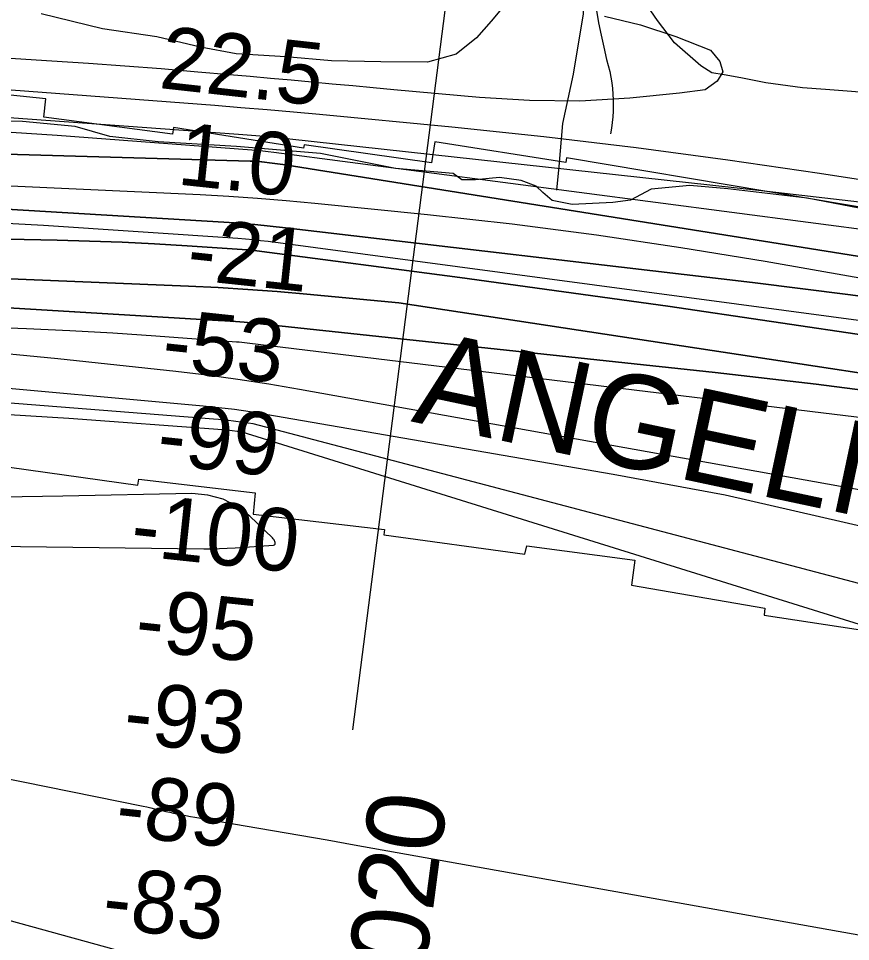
# Model space of a CAD drawing. Extents: x 3477039 to 3515015, y 546746 to 572297.
# Drawn here: x 3495983 to 3496874, y 565048 to 566036 of the extents above; entities that cross this region are included whole.
import ezdxf

# ---------------------------------------------------------------- set-up
doc = ezdxf.new("R2010")
doc.units = 0
for name, color, linetype in [('V-RIVR-EDGE', 7, 'Continuous'), ('V-RIVR-RANG', 7, 'Continuous'), ('V-RIVR-RANG-IDEN', 7, 'Continuous'), ('V-ROAD-CNTR', 7, 'Continuous'), ('V-RRAP-RVMT', 7, 'Continuous'), ('V-RRAP-RVMT-IDEN', 7, 'Continuous'), ('V-SITE-VEGE', 7, 'Continuous'), ('V-TOPO-DPTH', 7, 'Continuous'), ('V-TOPO-MAJR', 7, 'Continuous'), ('V-TOPO-MINR', 7, 'Continuous'), ('V-TOPO-WATR', 7, 'Continuous')]:
    doc.layers.add(name, color=color, linetype=linetype)

msp = doc.modelspace()

# ---------------------------------------------------------------- linework, layer by layer
at = {"layer": 'V-RIVR-EDGE'}
msp.add_lwpolyline([(3496957.3, 565818.57), (3496827.47, 565843.4), (3496742.32, 565853.41), (3496701.89, 565857.19), (3496660.21, 565853), (3496638.13, 565841.42), (3496619.13, 565839.01), (3496575.62, 565836.67), (3496554.18, 565841.01), (3496544.4, 565849.61), (3496537.06, 565856.37), (3496521.15, 565862.54), (3496497.87, 565865.66), (3496472.13, 565863.27), (3496457.43, 565863.31), (3496448.25, 565870.07), (3496386.38, 565875.13), (3496306.15, 565891.26), (3496216.1, 565898.83), (3496132.17, 565903.94), (3496080.71, 565909.58), (3496043.36, 565920.09), (3495987.01, 565925.74), (3495880.4, 565928.46)], dxfattribs=at)
at = {"layer": 'V-RIVR-RANG'}
msp.add_line((3496478.2, 566345.66), (3496340.49, 565274.48), dxfattribs=at)
at = {"layer": 'V-ROAD-CNTR'}
for points in [[(3496246.34, 566507.57), (3496245.2, 566482.09), (3496242.29, 566469.09), (3496260.5, 566457.13), (3496304.77, 566431.33), (3496358.02, 566406.36), (3496399.15, 566379.95), (3496450.2, 566355.13), (3496501.38, 566320.35), (3496535.86, 566296.37), (3496563.48, 566267.26), (3496579.75, 566242.09), (3496587.69, 566212.48), (3496588.84, 566175.79), (3496589.71, 566095.32), (3496587.65, 566040.76), (3496576.72, 565976.38), (3496565.34, 565923.65), (3496561.27, 565877.28), (3496558.82, 565852.14)], [(3496601.6, 566044.37), (3496604.05, 566031.24), (3496606.7, 566018.15), (3496609.56, 566005.1), (3496612.62, 565992.1), (3496615.88, 565979.14)], [(3496615.88, 565979.14), (3496617.09, 565973.15), (3496618.08, 565967.11), (3496618.84, 565961.04), (3496619.37, 565954.94), (3496619.67, 565948.83), (3496619.74, 565942.71), (3496619.58, 565936.6), (3496619.19, 565930.49), (3496618.58, 565924.4), (3496617.73, 565918.35), (3496616.65, 565912.33)]]:
    msp.add_lwpolyline(points, dxfattribs=at)
at = {"layer": 'V-RRAP-RVMT'}
for points in [[(3496428.75, 565903.82), (3496425.03, 565881.3), (3496288.73, 565900.79), (3496288.13, 565897.23), (3496148.81, 565919.33), (3496147.48, 565912.06), (3496010.02, 565930.31), (3496012.05, 565950.05), (3495887.88, 565962.86)], [(3498017.81, 565575.45), (3497871.45, 565614.89), (3497875.49, 565636.07), (3497723.36, 565670.25), (3497726.6, 565689.16), (3497585.89, 565716.82), (3497587.48, 565727.34), (3497446.64, 565753.6), (3497447.28, 565757.54), (3497148.03, 565804.73), (3497146.14, 565793.55), (3497004.18, 565819.67), (3497003.06, 565813.83), (3496569.66, 565886.55), (3496568.88, 565881.74), (3496428.75, 565903.82)], [(3495952.43, 565558.58), (3496110.6, 565536.17), (3496111.72, 565542.55), (3496236.14, 565527.94), (3496234.08, 565505.3), (3496374.74, 565488.82), (3496374.09, 565483.16), (3496525.18, 565462.33), (3496526.99, 565471.5), (3496642.67, 565455.88), (3496639.22, 565429.11), (3496782.19, 565404.78), (3496781.48, 565397.29), (3496929.02, 565374.81)]]:
    msp.add_lwpolyline(points, dxfattribs=at)
at = {"layer": 'V-SITE-VEGE'}
for points in [[(3497120.6, 566047.4), (3497218.33, 566003.77), (3497290.1, 565964.74), (3497333.04, 565944.44), (3497349.29, 565930.24), (3497355.18, 565922.04), (3497354.38, 565913.14), (3497347.63, 565900.56), (3497322.32, 565889.57), (3497261.49, 565895.87), (3497147.27, 565912.88), (3497006.37, 565938.21), (3496907, 565955.13), (3496846.9, 565959.94), (3496822.41, 565961.57), (3496783.1, 565967), (3496756.41, 565972.36), (3496738.61, 565975.43), (3496725.26, 565977.74), (3496713.43, 565985.23), (3496685.37, 566009.9), (3496666.95, 566033.76), (3496652.23, 566055.38)], [(3496503.68, 566050.45), (3496488.87, 566032.88), (3496473.08, 566015.31), (3496451.4, 565997.78), (3496420.94, 565989.12), (3496370.92, 565989.4), (3496317.95, 565990.68), (3496268.93, 565994.88), (3496215.98, 565998.12), (3496177.77, 566005.2), (3496130.74, 566016.26), (3496072.67, 566024.93), (3496006.92, 566040.72)]]:
    msp.add_lwpolyline(points, dxfattribs=at)
at = {"layer": 'V-TOPO-DPTH'}
for points in [[(3498160.46, 565543.63), (3497431.39, 565755.67), (3497421.88, 565758), (3497412.28, 565759.98), (3497402.63, 565761.72), (3497206.95, 565793.33), (3497099.32, 565809.88), (3496991.53, 565825.32), (3496883.52, 565839.1), (3496775.35, 565851.78), (3496273.4, 565906.72), (3496259.69, 565908.14), (3496245.98, 565909.46), (3496232.25, 565910.64), (3496218.51, 565911.71), (3495486.1, 565964.87)], [(3498512.82, 565373.8), (3497462.6, 565684.44), (3497434.89, 565690.67), (3497407.09, 565696.49), (3497379.18, 565701.69), (3497351.18, 565706.48), (3496277.27, 565877.71), (3496271.58, 565878.6), (3496265.88, 565879.45), (3496260.18, 565880.26), (3496254.47, 565881.03), (3496243.27, 565882.51), (3496243.04, 565882.54), (3496238.94, 565882.84), (3496236.89, 565882.98), (3496232.78, 565883.19), (3496230.72, 565883.27), (3494996.72, 565918.61)], [(3494996.72, 565918.61), (3496230.72, 565883.27), (3496232.78, 565883.19), (3496236.89, 565882.98), (3496238.94, 565882.84), (3496243.04, 565882.54), (3496243.27, 565882.51), (3496254.47, 565881.03), (3496260.18, 565880.26), (3496265.88, 565879.45), (3496271.58, 565878.6), (3496277.27, 565877.71), (3497351.18, 565706.48), (3497379.18, 565701.69), (3497407.09, 565696.49), (3497434.89, 565690.67), (3497462.6, 565684.44), (3498512.82, 565373.8)], [(3498451.12, 565366.82), (3497409.8, 565651.62), (3497403.42, 565653.27), (3497397.01, 565654.8), (3497390.57, 565656.16), (3497384.09, 565657.39), (3497188.25, 565691.92), (3497083.7, 565709.41), (3496978.98, 565725.7), (3496873.98, 565740.15), (3496768.81, 565753.39), (3496268.64, 565811.95), (3496252.2, 565813.73), (3496235.74, 565815.32), (3496219.25, 565816.64), (3496202.75, 565817.76), (3495712.9, 565846.95)], [(3495712.9, 565846.95), (3496202.75, 565817.76), (3496219.25, 565816.64), (3496235.74, 565815.32), (3496252.2, 565813.73), (3496268.64, 565811.95), (3496768.81, 565753.39), (3496873.98, 565740.15), (3496978.98, 565725.7), (3497083.7, 565709.41), (3497188.25, 565691.92), (3497384.09, 565657.39), (3497390.57, 565656.16), (3497397.01, 565654.8), (3497403.42, 565653.27), (3497409.8, 565651.62), (3498451.12, 565366.82)], [(3494999.93, 565819.44), (3496024.06, 565798.6), (3496058.88, 565797.66), (3496093.68, 565796.39), (3496128.47, 565794.64), (3496163.23, 565792.58), (3496227.66, 565788.31), (3496230.21, 565788.11), (3496232.74, 565787.89), (3496235.28, 565787.61), (3496237.81, 565787.3), (3496455.46, 565758.45), (3496566.77, 565743.35), (3496678.01, 565727.81), (3496789.16, 565711.6), (3496900.24, 565694.94), (3497312.27, 565631.89), (3497350.4, 565625.68), (3497388.45, 565618.99), (3497426.35, 565611.57), (3497464.17, 565603.68), (3497474.32, 565601.45), (3498461.05, 565311.54)], [(3494999.93, 565819.44), (3496024.06, 565798.6), (3496058.88, 565797.66), (3496093.68, 565796.39), (3496128.47, 565794.64), (3496163.23, 565792.58), (3496227.66, 565788.31), (3496230.21, 565788.11), (3496232.74, 565787.89), (3496235.28, 565787.61), (3496237.81, 565787.3), (3496455.46, 565758.45), (3496566.77, 565743.35), (3496678.01, 565727.81), (3496789.16, 565711.6), (3496900.24, 565694.94), (3497312.27, 565631.89), (3497350.4, 565625.68), (3497388.45, 565618.99), (3497426.35, 565611.57), (3497464.17, 565603.68), (3497474.32, 565601.45), (3498461.05, 565311.54)], [(3498478.51, 565276.24), (3497648.13, 565517.56), (3497414.72, 565572.26), (3497396.89, 565576.24), (3497379.01, 565579.99), (3497361.06, 565583.37), (3497343.06, 565586.5), (3496389.9, 565731.45), (3496291.58, 565740.73), (3496259.9, 565743.47), (3496228.21, 565745.87), (3496196.48, 565747.76), (3496164.72, 565749.31), (3495321.12, 565783.85)], [(3495321.12, 565783.85), (3496164.72, 565749.31), (3496196.48, 565747.76), (3496228.21, 565745.87), (3496259.9, 565743.47), (3496291.58, 565740.73), (3496389.9, 565731.45), (3497343.06, 565586.5), (3497361.06, 565583.37), (3497379.01, 565579.99), (3497396.89, 565576.24), (3497414.72, 565572.26), (3497648.13, 565517.56), (3498478.51, 565276.24)], [(3498486.89, 565258.7), (3497389.54, 565556.43), (3497381.88, 565558.32), (3497374.2, 565560.08), (3497366.47, 565561.64), (3497358.71, 565563.07), (3497159.74, 565597.17), (3497052.34, 565614.53), (3496944.75, 565630.53), (3496836.87, 565644.49), (3496728.8, 565657.09), (3496251.97, 565708.12), (3496238.17, 565709.5), (3496224.36, 565710.75), (3496210.53, 565711.8), (3496196.7, 565712.73), (3495888.85, 565731.14)], [(3495888.85, 565731.14), (3496196.7, 565712.73), (3496210.53, 565711.8), (3496224.36, 565710.75), (3496238.17, 565709.5), (3496251.97, 565708.12), (3496728.8, 565657.09), (3496836.87, 565644.49), (3496944.75, 565630.53), (3497052.34, 565614.53), (3497159.74, 565597.17), (3497358.71, 565563.07), (3497366.47, 565561.64), (3497374.2, 565560.08), (3497381.88, 565558.32), (3497389.54, 565556.43), (3498486.89, 565258.7)]]:
    msp.add_lwpolyline(points, dxfattribs=at)
at = {"layer": 'V-TOPO-MAJR'}
for points in [[(3498420.51, 565227.87), (3497577.65, 565489.3), (3497526.11, 565504.1), (3497474.46, 565518.55), (3497372.86, 565546.41), (3497370.07, 565547.07), (3497369.13, 565547.24), (3497345.59, 565551.26), (3497332.87, 565553.33), (3497320.12, 565555.29), (3497307.35, 565557.06), (3497294.56, 565558.7), (3496227.65, 565688.46), (3496224.83, 565688.78), (3496222, 565689.07), (3496219.17, 565689.33), (3496216.33, 565689.56), (3496129.8, 565695.86), (3496083.68, 565698.93), (3496037.54, 565701.62), (3495991.38, 565703.73), (3495945.19, 565705.47)], [(3496256.49, 565477.67), (3496255.63, 565478.83), (3496254.65, 565479.92), (3496230.65, 565503.04), (3496216.74, 565513.51), (3496201.87, 565521.48), (3496185.53, 565525.72), (3496168.22, 565527.46), (3496030.11, 565524.54), (3495942.91, 565522.93)], [(3495451.21, 565477.43), (3496181.2, 565468.21), (3496189.58, 565468.21), (3496197.95, 565468.35), (3496206.31, 565468.69), (3496214.68, 565469.17), (3496255.79, 565472.06), (3496256.81, 565472.47), (3496257.52, 565473.07), (3496257.79, 565473.97), (3496257.77, 565475.06), (3496256.49, 565477.67)]]:
    msp.add_lwpolyline(points, dxfattribs=at)
at = {"layer": 'V-TOPO-MINR'}
for points in [[(3496610.2, 566038.46), (3496648.87, 566028.93), (3496686.7, 566016.48), (3496723.96, 566002.1), (3496733.82, 565989.93), (3496737.21, 565978.64), (3496730.92, 565968.68), (3496718.15, 565959.6), (3496690.77, 565955.89), (3496637.29, 565950.49), (3496583.76, 565947.5), (3496530.14, 565948.16), (3496476.48, 565951.23), (3496384.7, 565959.62), (3496362.71, 565961.63), (3496340.72, 565963.65), (3496318.72, 565965.68), (3496296.73, 565967.71), (3496274.74, 565969.72), (3496252.74, 565971.71), (3496230.74, 565973.67), (3496208.74, 565975.6), (3496174.7, 565978.57), (3496135.67, 565981.84), (3496096.62, 565984.92), (3496057.56, 565987.74), (3496018.47, 565990.38), (3495030.91, 566053.6)], [(3498148.35, 565588.94), (3497719.16, 565706.24), (3497466.89, 565769.46), (3497446.9, 565774.17), (3497426.84, 565778.51), (3497406.67, 565782.3), (3497386.43, 565785.72), (3496840.72, 565870.07), (3496742.49, 565884.39), (3496644.11, 565897.57), (3496545.52, 565909.04), (3496446.79, 565919.38), (3496305.22, 565932.96), (3496277.16, 565935.57), (3496249.09, 565938.06), (3496221, 565940.39), (3496192.91, 565942.6), (3495637.84, 565984.62)], [(3498160.46, 565543.63), (3497431.39, 565755.67), (3497421.88, 565758), (3497412.28, 565759.98), (3497402.63, 565761.72), (3497206.95, 565793.33), (3497099.32, 565809.88), (3496991.53, 565825.32), (3496883.52, 565839.1), (3496775.35, 565851.78), (3496273.4, 565906.72), (3496259.69, 565908.14), (3496245.98, 565909.46), (3496232.25, 565910.64), (3496218.51, 565911.71), (3495486.1, 565964.87)], [(3498546.98, 565389.41), (3497441.94, 565732.9), (3497435.85, 565734.7), (3497429.74, 565736.46), (3497417.96, 565739.82), (3497417.29, 565739.98), (3497417.06, 565740.02), (3497411.93, 565740.88), (3497409.13, 565741.33), (3497406.33, 565741.76), (3497403.53, 565742.16), (3497400.72, 565742.54), (3496256.01, 565892.52), (3496250.15, 565893.24), (3496244.28, 565893.89), (3496238.4, 565894.45), (3496232.52, 565894.94), (3496024.21, 565910.68), (3495914.12, 565917.91)], [(3498520.98, 565356.7), (3497424.76, 565660.89), (3497412.34, 565663.87), (3497399.88, 565666.67), (3497387.36, 565669.2), (3497374.8, 565671.55), (3496782.33, 565775.73), (3496692.22, 565790.55), (3496601.94, 565804.06), (3496511.38, 565815.58), (3496420.63, 565825.78), (3496300.21, 565837.97), (3496269.52, 565840.83), (3496238.81, 565843.34), (3496208.06, 565845.35), (3496177.29, 565847.02), (3495239.54, 565890.07)], [(3498451.12, 565366.82), (3497409.8, 565651.62), (3497403.42, 565653.27), (3497397.01, 565654.8), (3497390.57, 565656.16), (3497384.09, 565657.39), (3497188.25, 565691.92), (3497083.7, 565709.41), (3496978.98, 565725.7), (3496873.98, 565740.15), (3496768.81, 565753.39), (3496268.64, 565811.95), (3496252.2, 565813.73), (3496235.74, 565815.32), (3496219.25, 565816.64), (3496202.75, 565817.76), (3495712.9, 565846.95)], [(3498461.05, 565311.54), (3497474.32, 565601.45), (3497464.17, 565603.68), (3497426.35, 565611.57), (3497388.45, 565618.99), (3497350.4, 565625.68), (3497312.27, 565631.89), (3496900.24, 565694.94), (3496789.16, 565711.6), (3496678.01, 565727.81), (3496566.77, 565743.35), (3496455.46, 565758.45), (3496237.81, 565787.3), (3496235.28, 565787.61), (3496232.74, 565787.89), (3496230.21, 565788.11), (3496227.66, 565788.31), (3496163.23, 565792.58), (3496128.47, 565794.64), (3496093.68, 565796.39), (3496058.88, 565797.66), (3496024.06, 565798.6), (3494999.93, 565819.44)], [(3498460.87, 565336.42), (3497503.13, 565613.11), (3497475.92, 565620.69), (3497448.68, 565628.19), (3497394.97, 565642.86), (3497394.57, 565642.96), (3497393.38, 565643.22), (3497381.04, 565645.4), (3497374.46, 565646.52), (3497367.88, 565647.58), (3497361.28, 565648.56), (3497354.68, 565649.49), (3496250.21, 565797.02), (3496242.08, 565798.02), (3496233.95, 565798.91), (3496225.79, 565799.65), (3496217.63, 565800.27), (3496009.4, 565814.12), (3495897.08, 565820.51)], [(3498478.51, 565276.24), (3497648.13, 565517.56), (3497414.72, 565572.26), (3497396.89, 565576.24), (3497379.01, 565579.99), (3497361.06, 565583.37), (3497343.06, 565586.5), (3496389.9, 565731.45), (3496291.58, 565740.73), (3496259.9, 565743.47), (3496228.21, 565745.87), (3496196.48, 565747.76), (3496164.72, 565749.31), (3495321.12, 565783.85)], [(3498486.89, 565258.7), (3497389.54, 565556.43), (3497381.88, 565558.32), (3497374.2, 565560.08), (3497366.47, 565561.64), (3497358.71, 565563.07), (3497159.74, 565597.17), (3497052.34, 565614.53), (3496944.75, 565630.53), (3496836.87, 565644.49), (3496728.8, 565657.09), (3496251.97, 565708.12), (3496238.17, 565709.5), (3496224.36, 565710.75), (3496210.53, 565711.8), (3496196.7, 565712.73), (3495888.85, 565731.14)], [(3498399.12, 565102.96), (3497397.61, 565366.85), (3497364.46, 565374.47), (3497331.38, 565382.34), (3497298.38, 565390.59), (3497265.45, 565399.09), (3497095.56, 565443.98), (3496739.46, 565525.44), (3496619.7, 565547.76), (3496247.71, 565612.04), (3496230.95, 565614.73), (3496214.16, 565617.15), (3496197.32, 565619.16), (3496180.43, 565620.9), (3495377.96, 565693.82)], [(3498448.45, 565154.2), (3497414.25, 565430.11), (3497397.48, 565434.57), (3497380.71, 565439.02), (3497347.19, 565447.9), (3497344.43, 565448.45), (3497341.69, 565448.98), (3497338.95, 565449.48), (3496283.8, 565638.86), (3496250.76, 565644.43), (3496217.66, 565649.54), (3496184.45, 565653.95), (3496151.18, 565657.88), (3496024.87, 565671.49), (3495928.32, 565680.91)], [(3498424.45, 565075.39), (3497290.41, 565311.85), (3497267.93, 565318.14), (3497094.98, 565367.9), (3497065.47, 565377.03), (3497036.25, 565386.95), (3497007.45, 565398.04), (3496234.07, 565601.81), (3496223.47, 565603.47), (3496212.84, 565604.93), (3496202.18, 565606.11), (3496191.49, 565607.09), (3495588.21, 565654.3)], [(3498302.74, 565009.38), (3497392.96, 565236.18), (3497347.39, 565247.89), (3497301.91, 565259.91), (3497256.55, 565272.38), (3497211.27, 565285.16), (3496222.27, 565592.9), (3496216.99, 565593.72), (3496211.7, 565594.44), (3496206.4, 565595.01), (3496201.08, 565595.48), (3496036.6, 565607.62), (3495949, 565613.02)], [(3495858.79, 565244.78), (3496116.27, 565192.68), (3496120.34, 565191.83), (3496124.4, 565190.94), (3496128.44, 565189.99), (3496132.48, 565189.01), (3496136.52, 565188.03), (3496140.56, 565187.08), (3496144.62, 565186.19), (3496148.69, 565185.33), (3496162.1, 565182.59), (3496166.83, 565181.67), (3496171.57, 565180.82), (3496225.37, 565171.7), (3496254.64, 565166.7), (3496283.9, 565161.65), (3496313.14, 565156.52), (3496342.38, 565151.35), (3497206.92, 564997.14)], [(3495949.71, 565076.79), (3496086.08, 565039.15)]]:
    msp.add_lwpolyline(points, dxfattribs=at)
at = {"layer": 'V-TOPO-WATR'}
msp.add_lwpolyline([(3498512.82, 565373.8), (3497462.6, 565684.44), (3497434.89, 565690.67), (3497407.09, 565696.49), (3497379.18, 565701.69), (3497351.18, 565706.48), (3496277.27, 565877.71), (3496271.58, 565878.6), (3496265.88, 565879.45), (3496260.18, 565880.26), (3496254.47, 565881.03), (3496243.27, 565882.51), (3496243.04, 565882.54), (3496238.94, 565882.84), (3496236.89, 565882.98), (3496232.78, 565883.19), (3496230.72, 565883.27), (3494996.72, 565918.61)], dxfattribs=at)

# ---------------------------------------------------------------- texts
at = {"layer": 'V-RIVR-RANG'}
for s, rotation, p in [('22.5', 353.64833, (3496132.15, 565961.57)), ('1.0', 353.93519, (3496151.6, 565858.34)), ('-21', 353.93519, (3496161.52, 565756.72)), ('-53', 353.93519, (3496134.7, 565659.01)), ('-99', 353.93519, (3496129.4, 565559.01)), ('-100', 353.93519, (3496101.28, 565461.44)), ('-95', 353.93519, (3496105.94, 565360.38)), ('-93', 353.93519, (3496093.56, 565261.13)), ('-89', 353.93519, (3496085.11, 565161.47)), ('-83', 353.93519, (3496070.89, 565062.41))]:
    msp.add_text(s, height=67, rotation=rotation, dxfattribs=at).set_placement(p)
at = {"layer": 'V-RIVR-RANG-IDEN'}
msp.add_text('D-020', height=83, rotation=82.53233, dxfattribs=at).set_placement((3496403.08, 564901.48))
at = {"layer": 'V-RRAP-RVMT-IDEN'}
msp.add_text('ANGELINA', height=100, rotation=348.01413, dxfattribs=at).set_placement((3496402.29, 565604.69))

doc.saveas('drawing.dxf')
